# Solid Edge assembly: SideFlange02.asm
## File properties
Author: ptcarter
Template: Normal.asm
Last saved by: ptcarter
Revision: 16
Application: Solid Edge
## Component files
SideFlange.par
ScrewM8.par
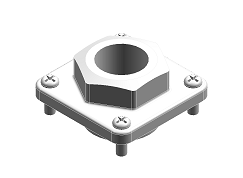
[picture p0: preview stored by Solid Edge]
